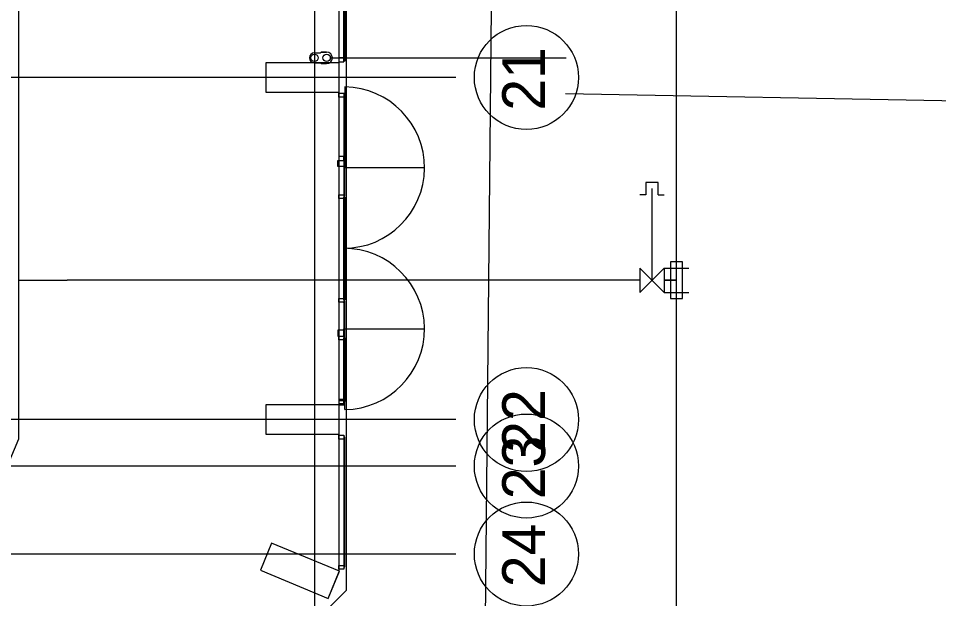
# Model space of a CAD drawing. Extents: x -264031 to -263588, y -1242281 to -1242059.
# Drawn here: x -263801.59 to -263782.79, y -1242227.54 to -1242215.67 of the extents above; entities that cross this region are included whole.
import ezdxf

# ---------------------------------------------------------------- set-up
doc = ezdxf.new("R2010")
doc.units = 0
for name, color, linetype in [('HESCON_OSI_STAVBY_KFA', 7, 'Continuous'), ('KFA_2D_SITUACIA_DSP', 7, 'Continuous'), ('KFA_JESTV_IS_DSP_-_KANAL_SPLASK', 7, 'Continuous')]:
    doc.layers.add(name, color=color, linetype=linetype)

msp = doc.modelspace()

# ---------------------------------------------------------------- linework, layer by layer
at = {"layer": 'HESCON_OSI_STAVBY_KFA'}
for p, q in [((-263795.543, -1242083.237), (-263795.543, -1242246.707)), ((-263792.653, -1242216.882), (-263911.523, -1242216.882)), ((-263792.653, -1242216.882), (-263792.653, -1242216.882)), ((-263792.653, -1242223.882), (-263911.523, -1242223.882)), ((-263792.653, -1242223.882), (-263792.653, -1242223.882)), ((-263792.653, -1242224.832), (-263911.523, -1242224.832)), ((-263792.653, -1242224.832), (-263792.653, -1242224.832)), ((-263792.653, -1242226.632), (-263911.523, -1242226.632)), ((-263792.653, -1242226.632), (-263792.653, -1242226.632))]:
    msp.add_line(p, q, dxfattribs=at)
for centre in [(-263791.21, -1242216.882), (-263791.21, -1242223.882), (-263791.21, -1242224.832), (-263791.21, -1242226.632)]:
    msp.add_circle(centre, 1.064, dxfattribs=at)
at = {"layer": 'KFA_2D_SITUACIA_DSP'}
for p, q in [((-263788.143, -1242250.14), (-263788.143, -1242082.64)), ((-263795.043, -1242101.769), (-263795.043, -1242226.995)), ((-263794.943, -1242216.552), (-263794.943, -1242214.452)), ((-263794.918, -1242214.452), (-263794.918, -1242216.552)), ((-263795.418, -1242216.379), (-263795.404, -1242216.365)), ((-263795.293, -1242216.365), (-263795.404, -1242216.365)), ((-263795.404, -1242216.365), (-263795.293, -1242216.365)), ((-263795.543, -1242216.379), (-263795.418, -1242216.379)), ((-263795.218, -1242216.482), (-263790.395, -1242216.482)), ((-263794.943, -1242216.482), (-263795.043, -1242216.482)), ((-263795.043, -1242216.482), (-263795.043, -1242216.562)), ((-263794.943, -1242216.522), (-263794.943, -1242216.482)), ((-263794.943, -1242216.562), (-263794.943, -1242216.522)), ((-263794.918, -1242216.552), (-263794.943, -1242216.552)), ((-263795.038, -1242216.582), (-263796.538, -1242216.582)), ((-263796.538, -1242216.582), (-263796.538, -1242217.182)), ((-263795.543, -1242216.585), (-263795.418, -1242216.585)), ((-263795.418, -1242216.585), (-263795.404, -1242216.599)), ((-263795.404, -1242216.599), (-263795.293, -1242216.599)), ((-263795.043, -1242216.562), (-263794.943, -1242216.562)), ((-263795.038, -1242217.182), (-263795.038, -1242216.582)), ((-263794.918, -1242217.077), (-263794.918, -1242218.727)), ((-263796.538, -1242217.182), (-263795.038, -1242217.182)), ((-263795.043, -1242217.282), (-263795.043, -1242217.202)), ((-263795.043, -1242217.202), (-263794.943, -1242217.202)), ((-263795.043, -1242217.282), (-263795.043, -1242217.202)), ((-263795.043, -1242217.202), (-263794.943, -1242217.202)), ((-263794.943, -1242217.282), (-263795.043, -1242217.282)), ((-263794.943, -1242217.282), (-263795.043, -1242217.282)), ((-263794.943, -1242217.202), (-263794.943, -1242217.242)), ((-263794.943, -1242217.202), (-263794.943, -1242217.242)), ((-263794.918, -1242217.212), (-263794.943, -1242217.212)), ((-263794.943, -1242217.212), (-263794.943, -1242219.312)), ((-263794.943, -1242217.242), (-263794.943, -1242217.282)), ((-263794.918, -1242217.242), (-263794.943, -1242217.242)), ((-263794.943, -1242217.242), (-263794.943, -1242218.542)), ((-263794.943, -1242217.242), (-263794.943, -1242217.282)), ((-263794.918, -1242219.312), (-263794.918, -1242217.212)), ((-263794.918, -1242218.542), (-263794.918, -1242217.242)), ((-263781.818, -1242217.375), (-263790.409, -1242217.218)), ((-263795.063, -1242218.702), (-263795.063, -1242218.582)), ((-263795.063, -1242218.582), (-263794.943, -1242218.582)), ((-263794.943, -1242218.502), (-263795.043, -1242218.502)), ((-263795.043, -1242218.502), (-263795.043, -1242218.582)), ((-263795.043, -1242218.582), (-263794.943, -1242218.582)), ((-263794.943, -1242218.542), (-263794.943, -1242218.502)), ((-263794.943, -1242218.542), (-263794.918, -1242218.542)), ((-263794.943, -1242218.582), (-263794.943, -1242218.542)), ((-263794.943, -1242218.582), (-263794.943, -1242218.702)), ((-263794.943, -1242218.702), (-263795.063, -1242218.702)), ((-263794.943, -1242218.702), (-263794.943, -1242218.727)), ((-263794.943, -1242218.727), (-263793.293, -1242218.727)), ((-263788.768, -1242219.032), (-263788.768, -1242219.282)), ((-263788.518, -1242219.032), (-263788.768, -1242219.032)), ((-263788.643, -1242221.032), (-263788.643, -1242219.157)), ((-263788.518, -1242219.282), (-263788.518, -1242219.032)), ((-263795.043, -1242219.362), (-263795.043, -1242219.282)), ((-263795.043, -1242219.282), (-263794.943, -1242219.282)), ((-263794.943, -1242219.362), (-263795.043, -1242219.362)), ((-263794.943, -1242219.282), (-263794.943, -1242219.322)), ((-263794.943, -1242219.312), (-263794.918, -1242219.312)), ((-263794.943, -1242219.322), (-263794.943, -1242219.362)), ((-263794.943, -1242221.432), (-263794.943, -1242219.332)), ((-263794.943, -1242219.332), (-263794.918, -1242219.332)), ((-263794.918, -1242219.332), (-263794.918, -1242221.432)), ((-263788.768, -1242219.282), (-263788.893, -1242219.282)), ((-263788.518, -1242219.282), (-263788.393, -1242219.282)), ((-263788.268, -1242220.657), (-263788.268, -1242221.407)), ((-263788.018, -1242220.657), (-263788.268, -1242220.657)), ((-263788.018, -1242221.407), (-263788.018, -1242220.657)), ((-263788.893, -1242220.782), (-263788.893, -1242221.282)), ((-263788.393, -1242221.282), (-263788.893, -1242220.782)), ((-263788.893, -1242221.282), (-263788.393, -1242220.782)), ((-263788.393, -1242220.782), (-263788.393, -1242221.282)), ((-263788.393, -1242220.782), (-263787.893, -1242220.782)), ((-263801.593, -1242221.032), (-263800.593, -1242221.032)), ((-263788.893, -1242221.032), (-263800.593, -1242221.032)), ((-263788.143, -1242221.032), (-263788.393, -1242221.032)), ((-263788.393, -1242221.032), (-263788.143, -1242221.032)), ((-263795.043, -1242221.482), (-263795.043, -1242221.402)), ((-263795.043, -1242221.402), (-263794.943, -1242221.402)), ((-263794.943, -1242221.402), (-263794.943, -1242221.492)), ((-263794.918, -1242221.432), (-263794.943, -1242221.432)), ((-263788.393, -1242221.282), (-263787.893, -1242221.282)), ((-263788.268, -1242221.407), (-263788.018, -1242221.407)), ((-263794.943, -1242221.482), (-263795.043, -1242221.482)), ((-263794.918, -1242221.452), (-263794.943, -1242221.452)), ((-263794.943, -1242221.452), (-263794.943, -1242223.552)), ((-263794.943, -1242221.492), (-263794.943, -1242221.482)), ((-263794.918, -1242223.552), (-263794.918, -1242221.452)), ((-263794.943, -1242222.052), (-263795.063, -1242222.052)), ((-263795.063, -1242222.052), (-263795.063, -1242222.172)), ((-263795.063, -1242222.172), (-263794.943, -1242222.172)), ((-263795.043, -1242222.252), (-263795.043, -1242222.172)), ((-263795.043, -1242222.172), (-263794.943, -1242222.172)), ((-263794.943, -1242222.052), (-263794.943, -1242222.027)), ((-263794.943, -1242222.027), (-263793.293, -1242222.027)), ((-263794.943, -1242222.172), (-263794.943, -1242222.052)), ((-263794.943, -1242222.172), (-263794.943, -1242222.212)), ((-263794.918, -1242223.677), (-263794.918, -1242222.027)), ((-263794.943, -1242222.252), (-263795.043, -1242222.252)), ((-263794.943, -1242223.512), (-263794.943, -1242222.212)), ((-263794.943, -1242222.212), (-263794.918, -1242222.212)), ((-263794.943, -1242222.212), (-263794.943, -1242222.252)), ((-263794.918, -1242222.212), (-263794.918, -1242223.512)), ((-263794.943, -1242223.472), (-263795.043, -1242223.472)), ((-263795.043, -1242223.472), (-263795.043, -1242223.552)), ((-263794.943, -1242223.497), (-263795.043, -1242223.497)), ((-263795.043, -1242223.497), (-263795.043, -1242223.577)), ((-263794.943, -1242223.512), (-263794.943, -1242223.472)), ((-263794.943, -1242223.537), (-263794.943, -1242223.497)), ((-263794.918, -1242223.512), (-263794.943, -1242223.512)), ((-263794.943, -1242223.552), (-263794.943, -1242223.512)), ((-263795.038, -1242223.582), (-263796.538, -1242223.582)), ((-263796.538, -1242223.582), (-263796.538, -1242224.182)), ((-263795.043, -1242223.552), (-263794.943, -1242223.552)), ((-263795.043, -1242223.577), (-263794.943, -1242223.577)), ((-263795.038, -1242224.182), (-263795.038, -1242223.582)), ((-263794.943, -1242223.577), (-263794.943, -1242223.537)), ((-263794.943, -1242223.552), (-263794.918, -1242223.552)), ((-263796.538, -1242224.182), (-263795.038, -1242224.182)), ((-263795.043, -1242224.282), (-263795.043, -1242224.202)), ((-263795.043, -1242224.202), (-263794.943, -1242224.202)), ((-263794.943, -1242224.202), (-263794.943, -1242224.242)), ((-263794.918, -1242224.242), (-263794.943, -1242224.242)), ((-263794.943, -1242224.242), (-263794.943, -1242226.892)), ((-263794.943, -1242224.242), (-263794.943, -1242224.282)), ((-263794.918, -1242226.892), (-263794.918, -1242224.242)), ((-263794.943, -1242224.282), (-263795.043, -1242224.282)), ((-263796.418, -1242226.411), (-263796.648, -1242226.966)), ((-263795.032, -1242226.985), (-263796.418, -1242226.411)), ((-263795.043, -1242226.945), (-263795.043, -1242226.865)), ((-263795.043, -1242226.865), (-263794.943, -1242226.865)), ((-263794.943, -1242226.865), (-263794.943, -1242226.905)), ((-263794.943, -1242226.892), (-263794.918, -1242226.892)), ((-263796.648, -1242226.966), (-263795.262, -1242227.54)), ((-263795.043, -1242226.995), (-263795.272, -1242227.55)), ((-263795.262, -1242227.54), (-263795.032, -1242226.985)), ((-263794.943, -1242226.945), (-263795.043, -1242226.945)), ((-263794.943, -1242226.905), (-263794.943, -1242226.945))]:
    msp.add_line(p, q, dxfattribs=at)
for points in [[(-263794.893, -1242227.382), (-263808.968, -1242241.457), (-263894.968, -1242241.457), (-263909.043, -1242227.382), (-263909.043, -1242196.333), (-263914.143, -1242196.333), (-263914.143, -1242132.433), (-263909.043, -1242132.433), (-263909.043, -1242101.382), (-263894.968, -1242087.307), (-263808.968, -1242087.307), (-263794.893, -1242101.382), (-263794.893, -1242227.382)], [(-263909.043, -1242125.432), (-263902.343, -1242125.432), (-263902.343, -1242104.482), (-263902.112, -1242103.927), (-263898.54, -1242100.355), (-263895.995, -1242097.81), (-263892.423, -1242094.238), (-263891.868, -1242094.007), (-263812.071, -1242094.007), (-263811.513, -1242094.238), (-263801.823, -1242103.927), (-263801.593, -1242104.482), (-263801.593, -1242224.282), (-263801.824, -1242224.838), (-263805.392, -1242228.407)]]:
    msp.add_lwpolyline(points, dxfattribs=at)
for centre in [(-263795.543, -1242216.482), (-263795.293, -1242216.482)]:
    msp.add_circle(centre, 0.075, dxfattribs=at)
for centre, radius, start, end in [((-263795.293, -1242216.482), 0.117, 270, 90), ((-263795.543, -1242216.482), 0.103, 90, 270), ((-263794.943, -1242218.727), 1.65, 270, 89.1318), ((-263794.943, -1242222.027), 1.65, 270.8682, 90)]:
    msp.add_arc(centre, radius, start, end, dxfattribs=at)
at = {"layer": 'KFA_JESTV_IS_DSP_-_KANAL_SPLASK'}
msp.add_line((-263791.929, -1242215.473), (-263792.293, -1242251.359), dxfattribs=at)

# ---------------------------------------------------------------- texts
at = {"layer": 'HESCON_OSI_STAVBY_KFA'}
for s, p in [('21', (-263790.829, -1242217.562)), ('22', (-263790.829, -1242224.562)), ('23', (-263790.829, -1242225.512)), ('24', (-263790.829, -1242227.312))]:
    msp.add_text(s, height=0.875, rotation=90, dxfattribs=at).set_placement(p)

doc.saveas('drawing.dxf')
